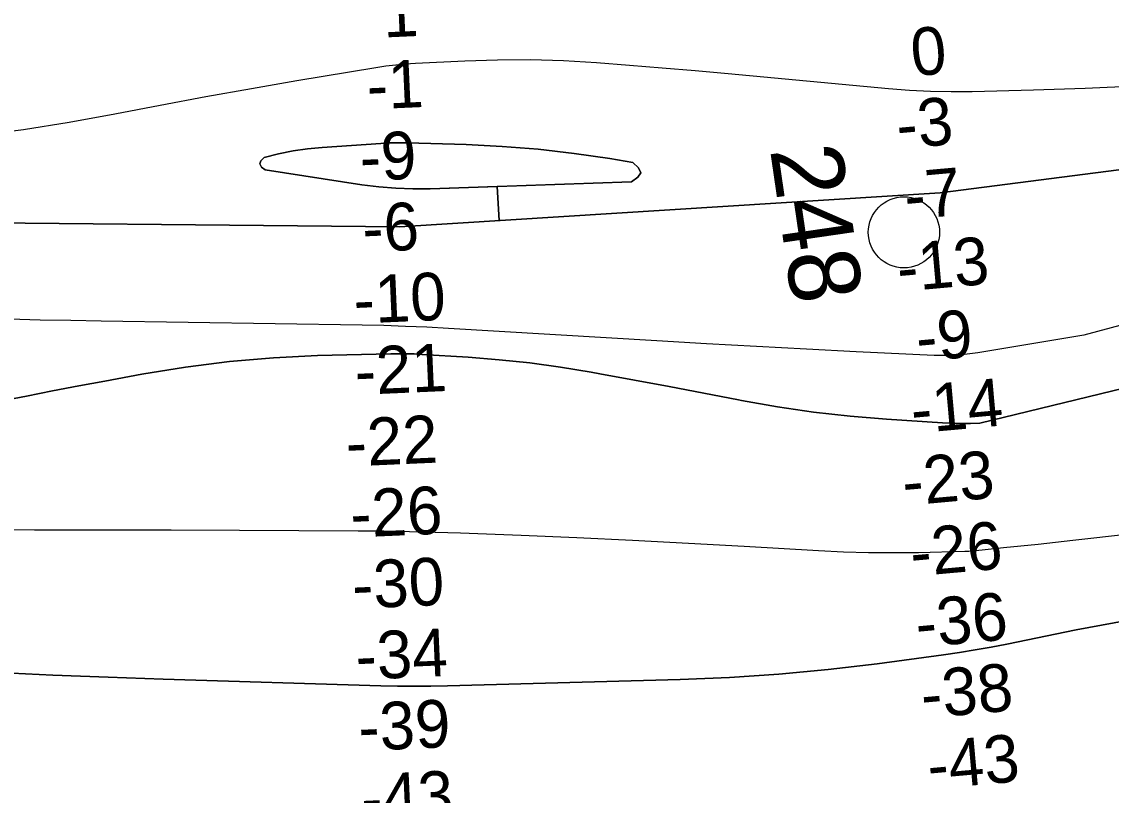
# Model space of a CAD drawing. Extents: x 3279314 to 3317160, y 734079 to 759431.
# Drawn here: x 3293839 to 3295369, y 752773 to 753859 of the extents above; entities that cross this region are included whole.
import ezdxf

# ---------------------------------------------------------------- set-up
doc = ezdxf.new("R2010")
doc.units = 0
for name, color, linetype in [('V-RIVR-IDEN', 7, 'Continuous'), ('V-RIVR-MILE', 7, 'Continuous'), ('V-RIVR-RANG', 7, 'Continuous'), ('V-TOPO-DPTH', 7, 'Continuous'), ('V-TOPO-MINR', 7, 'Continuous')]:
    doc.layers.add(name, color=color, linetype=linetype)

msp = doc.modelspace()

# ---------------------------------------------------------------- linework, layer by layer
at = {"layer": 'V-RIVR-MILE'}
msp.add_circle((3295077.9, 753563.5), 50, dxfattribs=at)
at = {"layer": 'V-TOPO-DPTH'}
for p, q in [((3295320, 753004.8), (3295391, 753018.3)), ((3295320, 753004.8), (3295391, 753018.3)), ((3295222.3, 752984.9), (3295320, 753004.8)), ((3295222.3, 752984.9), (3295320, 753004.8)), ((3295040.4, 752957.4), (3295133.6, 752969.9)), ((3295040.4, 752957.4), (3295133.6, 752969.9)), ((3295133.6, 752969.9), (3295155.9, 752973.2)), ((3295133.6, 752969.9), (3295155.9, 752973.2)), ((3295155.9, 752973.2), (3295178.1, 752976.7)), ((3295155.9, 752973.2), (3295178.1, 752976.7)), ((3295178.1, 752976.7), (3295200.2, 752980.6)), ((3295178.1, 752976.7), (3295200.2, 752980.6)), ((3295200.2, 752980.6), (3295222.3, 752984.9)), ((3295200.2, 752980.6), (3295222.3, 752984.9)), ((3294971.4, 752949.2), (3295040.4, 752957.4)), ((3294971.4, 752949.2), (3295040.4, 752957.4)), ((3293805.3, 752945), (3293882.8, 752941.5)), ((3293805.3, 752945), (3293882.8, 752941.5)), ((3293882.8, 752941.5), (3293960.3, 752938.5)), ((3293882.8, 752941.5), (3293960.3, 752938.5)), ((3294833, 752938.1), (3294902.3, 752942.6)), ((3294833, 752938.1), (3294902.3, 752942.6)), ((3294902.3, 752942.6), (3294971.4, 752949.2)), ((3294902.3, 752942.6), (3294971.4, 752949.2)), ((3293960.3, 752938.5), (3294037.9, 752935.8)), ((3293960.3, 752938.5), (3294037.9, 752935.8)), ((3294037.9, 752935.8), (3294343.3, 752926.3)), ((3294037.9, 752935.8), (3294343.3, 752926.3)), ((3294343.3, 752926.3), (3294366.7, 752925.8)), ((3294343.3, 752926.3), (3294366.7, 752925.8)), ((3294366.7, 752925.8), (3294390.1, 752925.6)), ((3294366.7, 752925.8), (3294390.1, 752925.6)), ((3294390.1, 752925.6), (3294413.5, 752925.7)), ((3294390.1, 752925.6), (3294413.5, 752925.7)), ((3294413.5, 752925.7), (3294436.9, 752926.2)), ((3294413.5, 752925.7), (3294436.9, 752926.2)), ((3294436.9, 752926.2), (3294763.6, 752935.1)), ((3294436.9, 752926.2), (3294763.6, 752935.1)), ((3294763.6, 752935.1), (3294833, 752938.1)), ((3294763.6, 752935.1), (3294833, 752938.1))]:
    msp.add_line(p, q, dxfattribs=at)
for points in [[(3294524, 753581), (3295128.6, 753618.9), (3295859.4, 753713), (3295893, 753716.9), (3295926.6, 753720.2), (3295960.2, 753722.8), (3295993.9, 753724.8), (3296723.4, 753758.7), (3297037.1, 753757.5), (3297086.8, 753756.3), (3297136.4, 753753.7)], [(3293604.7, 753578.5), (3294369.5, 753571.3), (3295128.6, 753618.9), (3295859.4, 753713)], [(3294364.5, 753625.4), (3294388.4, 753624.6), (3294412.4, 753624.8), (3294695.3, 753634.6), (3294704.3, 753640.8), (3294708.4, 753647.3), (3294705.2, 753654.2), (3294697.1, 753661.5), (3294664.8, 753667), (3294614.7, 753674.4), (3294564.4, 753680.4), (3294513.9, 753684.3), (3294463.3, 753686.8), (3294380.5, 753689.3), (3294371.1, 753689.4), (3294361.8, 753689.4), (3294352.5, 753689), (3294343.2, 753688.5), (3294261.1, 753682.9), (3294240.5, 753680.9), (3294220, 753678), (3294199.8, 753673.8), (3294179.7, 753668.8), (3294175, 753664), (3294173.2, 753659.5), (3294175.6, 753655.2), (3294180.8, 753651.2), (3294316.8, 753630.4), (3294340.6, 753627.4), (3294364.5, 753625.4)], [(3294364.5, 753625.4), (3294340.6, 753627.4), (3294316.8, 753630.4), (3294180.8, 753651.2), (3294175.6, 753655.2), (3294173.2, 753659.5), (3294175, 753664), (3294179.7, 753668.8), (3294199.8, 753673.8), (3294220, 753678), (3294240.5, 753680.9), (3294261.1, 753682.9), (3294343.2, 753688.5), (3294352.5, 753689), (3294361.8, 753689.4), (3294371.1, 753689.4), (3294380.5, 753689.3), (3294463.3, 753686.8), (3294513.9, 753684.3), (3294564.4, 753680.4), (3294614.7, 753674.4), (3294664.8, 753667), (3294697.1, 753661.5), (3294705.2, 753654.2), (3294708.4, 753647.3), (3294704.3, 753640.8), (3294695.3, 753634.6), (3294520.8, 753628.5), (3294506.7, 753628), (3294509.7, 753580.1), (3294524, 753581)], [(3294509.7, 753580.1), (3294506.7, 753628), (3294412.4, 753624.8), (3294388.4, 753624.6), (3294364.5, 753625.4)], [(3293604.7, 753578.5), (3294369.5, 753571.3), (3294509.7, 753580.1)], [(3295775.6, 753439.3), (3295184.3, 753295.2), (3295171.2, 753294.9), (3295158.2, 753294.9), (3295145.2, 753295.3), (3295132.1, 753295.9), (3295053.6, 753300.9), (3295002.3, 753305.1), (3294951.1, 753310.7), (3294900.3, 753318.4), (3294849.6, 753327.3), (3294845.8, 753328.1), (3294797.1, 753337.6), (3294748.4, 753346.9), (3294699.5, 753356), (3294650.7, 753364.9), (3294638.7, 753367.1), (3294595.7, 753374), (3294552.7, 753380), (3294509.4, 753384.5), (3294466, 753387.9), (3294400.8, 753392), (3294390, 753392.6), (3294379.1, 753392.9), (3294368.2, 753393), (3294357.3, 753392.8), (3294254.6, 753390.2), (3294192.5, 753387.2), (3294130.7, 753382.1), (3294069.1, 753374.2), (3294007.8, 753364.3), (3293955.9, 753354.6), (3293919.1, 753347.7), (3293882.4, 753340.7), (3293845.6, 753333.5), (3293808.9, 753326.3)], [(3293808.9, 753326.3), (3293845.6, 753333.5), (3293882.4, 753340.7), (3293919.1, 753347.7), (3293955.9, 753354.6), (3294007.8, 753364.3), (3294069.1, 753374.2), (3294130.7, 753382.1), (3294192.5, 753387.2), (3294254.6, 753390.2), (3294357.3, 753392.8), (3294368.2, 753393), (3294379.1, 753392.9), (3294390, 753392.6), (3294400.8, 753392), (3294466, 753387.9), (3294509.4, 753384.5), (3294552.7, 753380), (3294595.7, 753374), (3294638.7, 753367.1), (3294650.7, 753364.9), (3294699.5, 753356), (3294748.4, 753346.9), (3294797.1, 753337.6), (3294845.8, 753328.1), (3294849.6, 753327.3), (3294900.3, 753318.4), (3294951.1, 753310.7), (3295002.3, 753305.1), (3295053.6, 753300.9), (3295132.1, 753295.9), (3295145.2, 753295.3), (3295158.2, 753294.9), (3295171.2, 753294.9), (3295184.3, 753295.2), (3295775.6, 753439.3)], [(3295926.3, 753199), (3295315.1, 753130.4), (3295290.7, 753127.7), (3295266.4, 753125.1), (3295242, 753122.5), (3295217.7, 753120), (3295174.5, 753115.6), (3295171.7, 753115.4), (3295168.9, 753115.1), (3295166.2, 753115), (3295163.4, 753114.9), (3295098.6, 753113.4), (3295063.4, 753113), (3295028.3, 753113.2), (3294993.2, 753114.3), (3294958, 753116), (3294853.5, 753122.1), (3294775.2, 753126.5), (3294696.9, 753130.6), (3294618.6, 753134.2), (3294540.3, 753137.4), (3294455.4, 753140.7), (3294419.5, 753141.9), (3294383.6, 753142.9), (3294347.6, 753143.4), (3294311.7, 753143.8), (3294144.7, 753144.4), (3294048.9, 753144.8), (3293953, 753145), (3293857.2, 753145.2), (3293761.4, 753145.3)], [(3295926.3, 753199), (3295315.1, 753130.4), (3295290.7, 753127.7), (3295266.4, 753125.1), (3295242, 753122.5), (3295217.7, 753120), (3295174.5, 753115.6), (3295171.7, 753115.4), (3295168.9, 753115.1), (3295166.2, 753115), (3295163.4, 753114.9), (3295098.6, 753113.4), (3295063.4, 753113), (3295028.3, 753113.2), (3294993.2, 753114.3), (3294958, 753116), (3294853.5, 753122.1), (3294775.2, 753126.5), (3294696.9, 753130.6), (3294618.6, 753134.2), (3294540.3, 753137.4), (3294455.4, 753140.7), (3294419.5, 753141.9), (3294383.6, 753142.9), (3294347.6, 753143.4), (3294311.7, 753143.8), (3294144.7, 753144.4), (3294048.9, 753144.8), (3293953, 753145), (3293857.2, 753145.2), (3293761.4, 753145.3)]]:
    msp.add_lwpolyline(points, dxfattribs=at)
at = {"layer": 'V-TOPO-MINR'}
for p, q in [((3295391, 753018.3), (3295320, 753004.8)), ((3295320, 753004.8), (3295222.3, 752984.9)), ((3295133.6, 752969.9), (3295040.4, 752957.4)), ((3295155.9, 752973.2), (3295133.6, 752969.9)), ((3295178.1, 752976.7), (3295155.9, 752973.2)), ((3295200.2, 752980.6), (3295178.1, 752976.7)), ((3295222.3, 752984.9), (3295200.2, 752980.6)), ((3295040.4, 752957.4), (3294971.4, 752949.2)), ((3293882.8, 752941.5), (3293805.3, 752945)), ((3293960.3, 752938.5), (3293882.8, 752941.5)), ((3294902.3, 752942.6), (3294833, 752938.1)), ((3294971.4, 752949.2), (3294902.3, 752942.6)), ((3294037.9, 752935.8), (3293960.3, 752938.5)), ((3294343.3, 752926.3), (3294037.9, 752935.8)), ((3294366.7, 752925.8), (3294343.3, 752926.3)), ((3294390.1, 752925.6), (3294366.7, 752925.8)), ((3294413.5, 752925.7), (3294390.1, 752925.6)), ((3294436.9, 752926.2), (3294413.5, 752925.7)), ((3294763.6, 752935.1), (3294436.9, 752926.2)), ((3294833, 752938.1), (3294763.6, 752935.1))]:
    msp.add_line(p, q, dxfattribs=at)
for points in [[(3295405, 753768.8), (3295332.5, 753765.7), (3295260, 753763.3), (3295173.8, 753761), (3295144.4, 753760.8), (3295115, 753761.2), (3295085.6, 753762.7), (3295056.3, 753765), (3294830.9, 753786.1), (3294784.8, 753790.3), (3294738.6, 753794.3), (3294692.4, 753798.1), (3294646.2, 753801.7), (3294599.9, 753804.3), (3294553.7, 753805.7), (3294507.4, 753805.5), (3294461.1, 753804.1), (3294392.2, 753800.7), (3294378.2, 753799.8), (3294364.2, 753798.5), (3294350.2, 753796.8), (3294336.3, 753794.7), (3294225.6, 753776.2), (3294161.5, 753765.2), (3294097.5, 753753.8), (3294033.5, 753741.8), (3293969.7, 753729.4), (3293905.7, 753717.8), (3293841.5, 753707.6), (3293777.1, 753699.5)], [(3295859.4, 753713), (3295128.6, 753618.9), (3294369.5, 753571.3), (3293604.7, 753578.5)], [(3294364.5, 753625.4), (3294388.4, 753624.6), (3294412.4, 753624.8), (3294695.3, 753634.6), (3294704.3, 753640.8), (3294708.4, 753647.3), (3294705.2, 753654.2), (3294697.1, 753661.5), (3294664.8, 753667), (3294614.7, 753674.4), (3294564.4, 753680.4), (3294513.9, 753684.3), (3294463.3, 753686.8), (3294380.5, 753689.3), (3294371.1, 753689.4), (3294361.8, 753689.4), (3294352.5, 753689), (3294343.2, 753688.5), (3294261.1, 753682.9), (3294240.5, 753680.9), (3294220, 753678), (3294199.8, 753673.8), (3294179.7, 753668.8), (3294175, 753664), (3294173.2, 753659.5), (3294175.6, 753655.2), (3294180.8, 753651.2), (3294316.8, 753630.4), (3294340.6, 753627.4), (3294364.5, 753625.4)], [(3295920.3, 753577.5), (3295330.4, 753419), (3295181.8, 753394.1), (3295166.5, 753392.1), (3295151.1, 753390.6), (3295135.7, 753390.2), (3295120.2, 753390.5), (3295011, 753395.7), (3294940.9, 753399.2), (3294870.8, 753402.9), (3294800.7, 753406.8), (3294730.7, 753410.9), (3294438.2, 753428.5), (3294408, 753430.1), (3294377.8, 753431.4), (3294347.5, 753432.4), (3294317.3, 753433), (3293950.8, 753438.7), (3293907.9, 753439.4), (3293865, 753440.3), (3293822.1, 753441.3)], [(3295775.6, 753439.3), (3295184.3, 753295.2), (3295171.2, 753294.9), (3295158.2, 753294.9), (3295145.2, 753295.3), (3295132.1, 753295.9), (3295053.6, 753300.9), (3295002.3, 753305.1), (3294951.1, 753310.7), (3294900.3, 753318.4), (3294849.6, 753327.3), (3294845.8, 753328.1), (3294797.1, 753337.6), (3294748.4, 753346.9), (3294699.5, 753356), (3294650.7, 753364.9), (3294638.7, 753367.1), (3294595.7, 753374), (3294552.7, 753380), (3294509.4, 753384.5), (3294466, 753387.9), (3294400.8, 753392), (3294390, 753392.6), (3294379.1, 753392.9), (3294368.2, 753393), (3294357.3, 753392.8), (3294254.6, 753390.2), (3294192.5, 753387.2), (3294130.7, 753382.1), (3294069.1, 753374.2), (3294007.8, 753364.3), (3293955.9, 753354.6), (3293919.1, 753347.7), (3293882.4, 753340.7), (3293845.6, 753333.5), (3293808.9, 753326.3)], [(3295926.3, 753199), (3295315.1, 753130.4), (3295290.7, 753127.7), (3295266.4, 753125.1), (3295242, 753122.5), (3295217.7, 753120), (3295174.5, 753115.6), (3295171.7, 753115.4), (3295168.9, 753115.1), (3295166.2, 753115), (3295163.4, 753114.9), (3295098.6, 753113.4), (3295063.4, 753113), (3295028.3, 753113.2), (3294993.2, 753114.3), (3294958, 753116), (3294853.5, 753122.1), (3294775.2, 753126.5), (3294696.9, 753130.6), (3294618.6, 753134.2), (3294540.3, 753137.4), (3294455.4, 753140.7), (3294419.5, 753141.9), (3294383.6, 753142.9), (3294347.6, 753143.4), (3294311.7, 753143.8), (3294144.7, 753144.4), (3294048.9, 753144.8), (3293953, 753145), (3293857.2, 753145.2), (3293761.4, 753145.3)]]:
    msp.add_lwpolyline(points, dxfattribs=at)

# ---------------------------------------------------------------- texts
at = {"layer": 'V-RIVR-IDEN'}
msp.add_text('248', height=100, rotation=278.3025, dxfattribs=at).set_placement((3294889.8, 753679.8))
msp.add_text('248', height=100, rotation=278.3025, dxfattribs=at).set_placement((3294889.8, 753679.8))
at = {"layer": 'V-RIVR-RANG'}
for s, rotation, p in [('1', 2.5399, (3294347.4, 753837.2)), ('0', 5.1403, (3295090.5, 753782.7)), ('-1', 2.5399, (3294324.9, 753736.1)), ('-3', 5.1403, (3295069.9, 753680.5)), ('-9', 2.5399, (3294315, 753635.5)), ('-7', 5.1403, (3295081.1, 753581.1)), ('-6', 2.5399, (3294318.6, 753535.6)), ('-13', 5.1403, (3295070.8, 753479.8)), ('-10', 2.5399, (3294306.3, 753435)), ('-9', 5.1403, (3295097.5, 753381.8)), ('-21', 2.5399, (3294308, 753334.9)), ('-14', 5.1403, (3295090.3, 753280.7)), ('-22', 2.5399, (3294295.3, 753234.3)), ('-23', 5.1403, (3295078.2, 753179.2)), ('-26', 2.5399, (3294301.7, 753134.5)), ('-26', 5.1403, (3295089.4, 753079.8)), ('-30', 2.5399, (3294304.2, 753034.5)), ('-36', 5.1403, (3295096.9, 752980.1)), ('-34', 2.5399, (3294309.1, 752934.6)), ('-38', 5.1403, (3295104.4, 752880.4)), ('-39', 2.5399, (3294313, 752834.7)), ('-43', 5.1403, (3295113.5, 752780.8)), ('-43', 2.5399, (3294317, 752734.8))]:
    msp.add_text(s, height=67, rotation=rotation, dxfattribs=at).set_placement(p)

doc.saveas('drawing.dxf')
